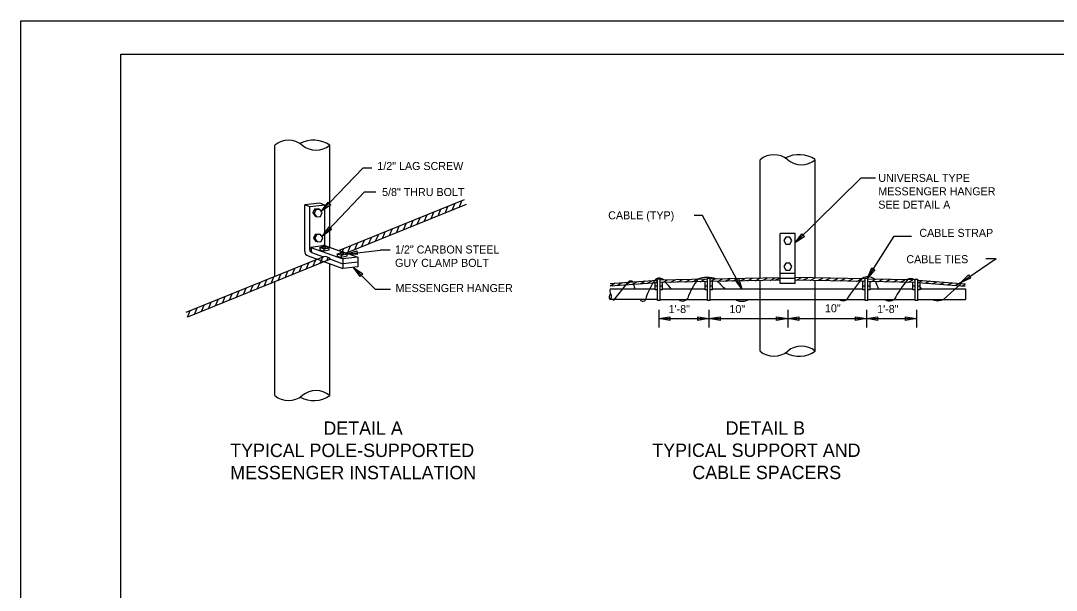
# Model space of a CAD drawing. Extents: x 1299104.8 to 1299141.6, y 239639.8 to 239661.8.
# Drawn here: x 1299104.8 to 1299120.32, y 239653.26 to 239661.79 of the extents above; entities that cross this region are included whole.
import ezdxf

# ---------------------------------------------------------------- set-up
doc = ezdxf.new("R2010")
doc.units = 0
for name, color, linetype in [('DIM TXT', 7, 'Continuous'), ('GS_plotshape_p', 7, 'Continuous'), ('Level 1', 7, 'Continuous')]:
    doc.layers.add(name, color=color, linetype=linetype)

msp = doc.modelspace()

# ---------------------------------------------------------------- linework, layer by layer
at = {"layer": 'DIM TXT'}
for p, q in [((1299108.609, 239657.959), (1299108.609, 239659.926)), ((1299109.434, 239658.399), (1299109.434, 239659.926)), ((1299115.885, 239657.936), (1299115.885, 239659.709)), ((1299116.71, 239657.938), (1299116.71, 239659.709)), ((1299109.928, 239659.584), (1299109.312, 239658.936)), ((1299110.066, 239659.584), (1299109.928, 239659.584)), ((1299116.41, 239658.462), (1299117.396, 239659.436)), ((1299117.396, 239659.436), (1299117.611, 239659.436)), ((1299109.955, 239659.227), (1299109.325, 239658.566)), ((1299109.955, 239659.227), (1299110.125, 239659.227)), ((1299109.284, 239659.056), (1299109.059, 239659.032)), ((1299109.059, 239658.338), (1299109.059, 239659.032)), ((1299109.134, 239659.002), (1299109.059, 239659.032)), ((1299109.359, 239659.026), (1299109.134, 239659.002)), ((1299109.359, 239659.026), (1299109.284, 239659.056)), ((1299109.359, 239658.426), (1299109.359, 239659.026)), ((1299111.448, 239659.106), (1299109.573, 239658.348)), ((1299111.477, 239659.036), (1299109.678, 239658.31)), ((1299111.164, 239658.91), (1299111.205, 239659.008)), ((1299111.268, 239658.952), (1299111.309, 239659.05)), ((1299111.372, 239658.994), (1299111.414, 239659.092)), ((1299109.134, 239658.357), (1299109.134, 239659.002)), ((1299109.198, 239658.904), (1299109.178, 239658.911)), ((1299109.223, 239658.959), (1299109.203, 239658.966)), ((1299109.233, 239658.854), (1299109.214, 239658.862)), ((1299109.283, 239658.965), (1299109.264, 239658.972)), ((1299110.851, 239658.784), (1299110.892, 239658.881)), ((1299110.955, 239658.826), (1299110.996, 239658.923)), ((1299111.059, 239658.868), (1299111.101, 239658.966)), ((1299115.018, 239658.875), (1299114.897, 239658.875)), ((1299115.612, 239657.773), (1299115.018, 239658.875)), ((1299110.434, 239658.615), (1299110.475, 239658.713)), ((1299110.538, 239658.657), (1299110.579, 239658.755)), ((1299110.642, 239658.699), (1299110.684, 239658.797)), ((1299110.746, 239658.741), (1299110.788, 239658.839)), ((1299109.233, 239658.582), (1299109.214, 239658.59)), ((1299109.293, 239658.588), (1299109.274, 239658.596)), ((1299110.016, 239658.446), (1299110.058, 239658.544)), ((1299110.121, 239658.489), (1299110.162, 239658.586)), ((1299110.225, 239658.531), (1299110.266, 239658.628)), ((1299110.329, 239658.573), (1299110.371, 239658.671)), ((1299116.185, 239657.853), (1299116.185, 239658.603)), ((1299116.41, 239658.603), (1299116.185, 239658.603)), ((1299116.267, 239658.55), (1299116.237, 239658.497)), ((1299116.327, 239658.55), (1299116.267, 239658.55)), ((1299116.358, 239658.498), (1299116.327, 239658.55)), ((1299116.41, 239657.853), (1299116.41, 239658.603)), ((1299117.493, 239657.934), (1299117.891, 239658.565)), ((1299117.891, 239658.565), (1299118.154, 239658.565)), ((1299109.359, 239658.426), (1299109.151, 239658.396)), ((1299109.151, 239658.396), (1299109.628, 239658.222)), ((1299109.151, 239658.396), (1299109.159, 239658.321)), ((1299109.208, 239658.527), (1299109.189, 239658.534)), ((1299109.243, 239658.478), (1299109.224, 239658.485)), ((1299109.286, 239658.396), (1299109.331, 239658.407)), ((1299109.286, 239658.396), (1299109.351, 239658.372)), ((1299109.286, 239658.396), (1299109.286, 239658.361)), ((1299109.331, 239658.394), (1299109.331, 239658.417)), ((1299109.351, 239658.373), (1299109.425, 239658.39)), ((1299109.359, 239658.426), (1299109.622, 239658.331)), ((1299109.372, 239658.392), (1299109.372, 239658.417)), ((1299109.372, 239658.409), (1299109.425, 239658.39)), ((1299109.425, 239658.355), (1299109.425, 239658.39)), ((1299109.703, 239658.32), (1299109.745, 239658.418)), ((1299109.808, 239658.362), (1299109.849, 239658.46)), ((1299109.912, 239658.404), (1299109.953, 239658.502)), ((1299116.237, 239658.497), (1299116.267, 239658.445)), ((1299116.267, 239658.445), (1299116.328, 239658.445)), ((1299116.328, 239658.445), (1299116.358, 239658.498)), ((1299109.342, 239658.255), (1299107.276, 239657.42)), ((1299109.109, 239658.268), (1299109.628, 239658.079)), ((1299109.159, 239658.321), (1299109.342, 239658.255)), ((1299109.286, 239658.361), (1299109.351, 239658.338)), ((1299109.286, 239658.151), (1299109.328, 239658.249)), ((1299109.351, 239658.338), (1299109.351, 239658.372)), ((1299109.425, 239658.355), (1299109.351, 239658.338)), ((1299109.39, 239658.194), (1299109.412, 239658.245)), ((1299109.547, 239658.301), (1299109.601, 239658.314)), ((1299109.547, 239658.301), (1299109.547, 239658.266)), ((1299109.547, 239658.301), (1299109.612, 239658.278)), ((1299109.547, 239658.266), (1299109.612, 239658.243)), ((1299109.601, 239658.3), (1299109.601, 239658.324)), ((1299109.612, 239658.278), (1299109.695, 239658.297)), ((1299109.612, 239658.243), (1299109.612, 239658.278)), ((1299109.695, 239658.262), (1299109.612, 239658.243)), ((1299109.621, 239658.331), (1299109.64, 239658.376)), ((1299109.853, 239658.247), (1299109.628, 239658.222)), ((1299109.641, 239658.299), (1299109.641, 239658.324)), ((1299109.641, 239658.317), (1299109.695, 239658.297)), ((1299109.644, 239658.322), (1299109.853, 239658.247)), ((1299109.677, 239658.293), (1299110.189, 239658.355)), ((1299109.695, 239658.262), (1299109.695, 239658.297)), ((1299109.853, 239658.247), (1299109.853, 239658.103)), ((1299110.338, 239658.355), (1299110.189, 239658.355)), ((1299118.886, 239657.866), (1299119.423, 239658.23)), ((1299119.268, 239658.23), (1299119.423, 239658.23)), ((1299109.447, 239658.217), (1299107.304, 239657.351)), ((1299108.869, 239657.983), (1299108.91, 239658.081)), ((1299108.973, 239658.025), (1299109.015, 239658.123)), ((1299109.078, 239658.067), (1299109.119, 239658.165)), ((1299109.182, 239658.109), (1299109.223, 239658.207)), ((1299109.434, 239656.176), (1299109.434, 239658.149)), ((1299109.447, 239658.217), (1299109.628, 239658.151)), ((1299109.628, 239658.222), (1299109.628, 239658.079)), ((1299109.853, 239658.175), (1299109.628, 239658.151)), ((1299109.853, 239658.103), (1299109.628, 239658.079)), ((1299110.12, 239657.764), (1299109.79, 239658.096)), ((1299108.556, 239657.856), (1299108.597, 239657.954)), ((1299108.66, 239657.899), (1299108.702, 239657.996)), ((1299108.765, 239657.941), (1299108.806, 239658.038)), ((1299114.347, 239657.6), (1299114.347, 239657.924)), ((1299114.347, 239657.924), (1299114.385, 239657.924)), ((1299115.096, 239657.921), (1299114.384, 239657.907)), ((1299114.385, 239657.6), (1299114.385, 239657.924)), ((1299114.985, 239657.881), (1299115.059, 239657.92)), ((1299115.097, 239657.937), (1299115.135, 239657.937)), ((1299115.097, 239657.6), (1299115.097, 239657.937)), ((1299116.184, 239657.942), (1299115.134, 239657.921)), ((1299115.135, 239657.6), (1299115.135, 239657.937)), ((1299115.135, 239657.884), (1299115.209, 239657.923)), ((1299115.247, 239657.886), (1299115.321, 239657.925)), ((1299115.36, 239657.888), (1299115.434, 239657.927)), ((1299115.472, 239657.89), (1299115.546, 239657.929)), ((1299115.585, 239657.893), (1299115.659, 239657.932)), ((1299115.697, 239657.894), (1299115.771, 239657.933)), ((1299115.81, 239657.897), (1299115.884, 239657.936)), ((1299115.922, 239657.899), (1299115.996, 239657.938)), ((1299116.035, 239657.901), (1299116.109, 239657.94)), ((1299116.11, 239657.903), (1299116.183, 239657.939)), ((1299116.41, 239658.003), (1299116.185, 239658.003)), ((1299116.41, 239657.928), (1299116.185, 239657.928)), ((1299117.461, 239657.923), (1299116.411, 239657.944)), ((1299116.428, 239657.907), (1299116.503, 239657.944)), ((1299116.523, 239657.904), (1299116.598, 239657.94)), ((1299116.635, 239657.902), (1299116.711, 239657.938)), ((1299116.747, 239657.9), (1299116.823, 239657.936)), ((1299116.86, 239657.898), (1299116.936, 239657.934)), ((1299116.972, 239657.895), (1299117.048, 239657.931)), ((1299117.085, 239657.893), (1299117.161, 239657.929)), ((1299117.197, 239657.891), (1299117.273, 239657.927)), ((1299117.33, 239657.885), (1299117.405, 239657.923)), ((1299117.46, 239657.6), (1299117.46, 239657.934)), ((1299117.46, 239657.934), (1299117.497, 239657.934)), ((1299117.497, 239657.6), (1299117.497, 239657.934)), ((1299118.21, 239657.908), (1299117.498, 239657.922)), ((1299118.21, 239657.6), (1299118.21, 239657.921)), ((1299118.21, 239657.921), (1299118.247, 239657.921)), ((1299118.247, 239657.6), (1299118.247, 239657.921)), ((1299108.139, 239657.688), (1299108.18, 239657.786)), ((1299108.243, 239657.73), (1299108.284, 239657.828)), ((1299108.347, 239657.772), (1299108.389, 239657.87)), ((1299108.452, 239657.814), (1299108.493, 239657.912)), ((1299108.609, 239656.176), (1299108.609, 239657.878)), ((1299113.635, 239657.857), (1299114.346, 239657.907)), ((1299113.635, 239657.773), (1299114.31, 239657.773)), ((1299113.636, 239657.82), (1299114.347, 239657.87)), ((1299113.636, 239657.82), (1299113.71, 239657.863)), ((1299113.691, 239657.607), (1299113.906, 239657.876)), ((1299113.748, 239657.828), (1299113.822, 239657.87)), ((1299113.86, 239657.836), (1299113.934, 239657.878)), ((1299113.906, 239657.876), (1299113.928, 239657.893)), ((1299113.928, 239657.893), (1299113.956, 239657.897)), ((1299113.956, 239657.897), (1299113.968, 239657.895)), ((1299113.968, 239657.895), (1299113.972, 239657.881)), ((1299113.973, 239657.843), (1299114.047, 239657.886)), ((1299113.985, 239657.844), (1299113.985, 239657.842)), ((1299114.085, 239657.851), (1299114.159, 239657.894)), ((1299114.198, 239657.859), (1299114.271, 239657.902)), ((1299114.31, 239657.867), (1299114.347, 239657.889)), ((1299114.31, 239657.758), (1299114.31, 239657.868)), ((1299114.347, 239657.814), (1299114.31, 239657.814)), ((1299115.097, 239657.883), (1299114.385, 239657.87)), ((1299114.422, 239657.814), (1299114.385, 239657.814)), ((1299114.422, 239657.87), (1299114.497, 239657.909)), ((1299114.422, 239657.758), (1299114.422, 239657.87)), ((1299114.422, 239657.773), (1299115.06, 239657.773)), ((1299114.535, 239657.872), (1299114.609, 239657.911)), ((1299114.647, 239657.875), (1299114.722, 239657.914)), ((1299114.76, 239657.877), (1299114.834, 239657.916)), ((1299114.872, 239657.879), (1299114.947, 239657.918)), ((1299115.06, 239657.758), (1299115.06, 239657.883)), ((1299115.097, 239657.814), (1299115.06, 239657.814)), ((1299116.184, 239657.904), (1299115.135, 239657.884)), ((1299115.172, 239657.814), (1299115.135, 239657.814)), ((1299115.172, 239657.758), (1299115.172, 239657.885)), ((1299115.172, 239657.773), (1299117.422, 239657.773)), ((1299115.885, 239656.841), (1299115.885, 239657.898)), ((1299116.41, 239657.853), (1299116.185, 239657.853)), ((1299116.41, 239657.87), (1299116.41, 239657.908)), ((1299117.46, 239657.885), (1299116.41, 239657.907)), ((1299116.71, 239656.841), (1299116.71, 239657.901)), ((1299117.422, 239657.758), (1299117.422, 239657.886)), ((1299117.46, 239657.814), (1299117.422, 239657.814)), ((1299117.424, 239657.885), (1299117.462, 239657.904)), ((1299118.21, 239657.87), (1299117.497, 239657.885)), ((1299117.535, 239657.814), (1299117.497, 239657.814)), ((1299117.535, 239657.758), (1299117.535, 239657.884)), ((1299117.535, 239657.773), (1299118.172, 239657.773)), ((1299117.541, 239657.881), (1299117.616, 239657.919)), ((1299117.647, 239657.882), (1299117.723, 239657.918)), ((1299117.76, 239657.879), (1299117.835, 239657.915)), ((1299117.872, 239657.877), (1299117.948, 239657.913)), ((1299117.985, 239657.875), (1299118.06, 239657.911)), ((1299118.097, 239657.872), (1299118.173, 239657.908)), ((1299118.172, 239657.758), (1299118.172, 239657.87)), ((1299118.21, 239657.814), (1299118.172, 239657.814)), ((1299118.247, 239657.87), (1299118.324, 239657.902)), ((1299118.247, 239657.87), (1299118.958, 239657.815)), ((1299118.285, 239657.814), (1299118.247, 239657.814)), ((1299118.249, 239657.907), (1299118.96, 239657.852)), ((1299118.285, 239657.758), (1299118.285, 239657.869)), ((1299118.285, 239657.773), (1299118.96, 239657.773)), ((1299118.358, 239657.861), (1299118.434, 239657.893)), ((1299118.469, 239657.853), (1299118.545, 239657.885)), ((1299118.58, 239657.844), (1299118.656, 239657.876)), ((1299118.897, 239657.857), (1299118.634, 239657.613)), ((1299118.69, 239657.836), (1299118.767, 239657.867)), ((1299118.801, 239657.827), (1299118.877, 239657.859)), ((1299118.912, 239657.819), (1299118.959, 239657.838)), ((1299118.96, 239657.773), (1299118.96, 239657.613)), ((1299107.72, 239657.519), (1299107.761, 239657.616)), ((1299107.824, 239657.561), (1299107.866, 239657.658)), ((1299107.929, 239657.603), (1299107.97, 239657.701)), ((1299108.034, 239657.646), (1299108.076, 239657.743)), ((1299110.345, 239657.764), (1299110.12, 239657.764)), ((1299114.347, 239657.613), (1299113.635, 239657.613)), ((1299114.347, 239657.758), (1299114.31, 239657.758)), ((1299114.422, 239657.758), (1299114.385, 239657.758)), ((1299114.385, 239657.613), (1299115.097, 239657.613)), ((1299115.097, 239657.758), (1299115.06, 239657.758)), ((1299115.172, 239657.758), (1299115.135, 239657.758)), ((1299115.135, 239657.613), (1299116.834, 239657.613)), ((1299116.834, 239657.613), (1299117.46, 239657.613)), ((1299117.46, 239657.758), (1299117.422, 239657.758)), ((1299117.535, 239657.758), (1299117.497, 239657.758)), ((1299117.497, 239657.613), (1299118.21, 239657.613)), ((1299118.21, 239657.758), (1299118.172, 239657.758)), ((1299118.285, 239657.758), (1299118.247, 239657.758)), ((1299118.247, 239657.613), (1299118.96, 239657.613)), ((1299107.407, 239657.392), (1299107.448, 239657.49)), ((1299107.511, 239657.434), (1299107.553, 239657.532)), ((1299107.616, 239657.477), (1299107.657, 239657.574)), ((1299114.385, 239657.6), (1299114.347, 239657.6)), ((1299114.366, 239657.46), (1299114.366, 239657.197)), ((1299115.135, 239657.6), (1299115.097, 239657.6)), ((1299115.116, 239657.46), (1299115.116, 239657.197)), ((1299116.297, 239657.462), (1299116.297, 239657.197)), ((1299117.497, 239657.6), (1299117.46, 239657.6)), ((1299117.478, 239657.46), (1299117.478, 239657.197)), ((1299118.247, 239657.6), (1299118.21, 239657.6)), ((1299118.228, 239657.46), (1299118.228, 239657.197)), ((1299107.303, 239657.35), (1299107.344, 239657.448)), ((1299114.366, 239657.328), (1299118.228, 239657.328))]:
    msp.add_line(p, q, dxfattribs=at)
for points in [[(1299109.41, 239659.074), (1299109.448, 239659.035), (1299109.312, 239658.936)], [(1299109.423, 239658.703), (1299109.462, 239658.665), (1299109.325, 239658.566)], [(1299116.511, 239658.597), (1299116.549, 239658.558), (1299116.41, 239658.462)], [(1299109.839, 239658.342), (1299109.846, 239658.288), (1299109.677, 239658.293)], [(1299109.927, 239657.997), (1299109.888, 239657.959), (1299109.79, 239658.096)], [(1299117.558, 239658.09), (1299117.605, 239658.061), (1299117.493, 239657.934)], [(1299115.511, 239657.908), (1299115.559, 239657.933), (1299115.612, 239657.773)], [(1299119.009, 239657.982), (1299119.039, 239657.936), (1299118.886, 239657.866)], [(1299114.533, 239657.356), (1299114.533, 239657.301), (1299114.366, 239657.328)], [(1299114.949, 239657.301), (1299114.949, 239657.356), (1299115.116, 239657.328)], [(1299115.283, 239657.356), (1299115.283, 239657.301), (1299115.116, 239657.328)], [(1299116.13, 239657.301), (1299116.13, 239657.356), (1299116.297, 239657.328)], [(1299116.464, 239657.356), (1299116.464, 239657.301), (1299116.297, 239657.328)], [(1299117.312, 239657.301), (1299117.312, 239657.356), (1299117.478, 239657.328)], [(1299117.645, 239657.356), (1299117.645, 239657.301), (1299117.478, 239657.328)], [(1299118.062, 239657.301), (1299118.062, 239657.356), (1299118.228, 239657.328)]]:
    msp.add_lwpolyline(points, close=True, dxfattribs=at)
for points in [[(1299109.203, 239658.966), (1299109.178, 239658.911), (1299109.214, 239658.862)], [(1299109.223, 239658.959), (1299109.198, 239658.904), (1299109.233, 239658.854), (1299109.293, 239658.86), (1299109.318, 239658.916)], [(1299109.264, 239658.972), (1299109.203, 239658.966)], [(1299109.318, 239658.916), (1299109.283, 239658.965), (1299109.223, 239658.959)], [(1299109.214, 239658.59), (1299109.189, 239658.534), (1299109.224, 239658.485)], [(1299109.233, 239658.582), (1299109.208, 239658.527), (1299109.243, 239658.478), (1299109.304, 239658.484), (1299109.329, 239658.539)], [(1299109.274, 239658.596), (1299109.214, 239658.59)], [(1299109.329, 239658.539), (1299109.293, 239658.588), (1299109.233, 239658.582)], [(1299116.267, 239658.16), (1299116.237, 239658.108), (1299116.267, 239658.055), (1299116.327, 239658.055), (1299116.358, 239658.107)], [(1299116.358, 239658.107), (1299116.328, 239658.16), (1299116.267, 239658.16)]]:
    msp.add_lwpolyline(points, dxfattribs=at)
for centre, radius, start, end in [((1299108.816, 239659.68), 0.321, 50.0338, 129.9662), ((1299109.191, 239659.567), 0.434, 55.7945, 117.8517), ((1299109.228, 239660.172), 0.321, 230.0338, 309.9662), ((1299116.091, 239659.463), 0.321, 50.0338, 129.9662), ((1299116.466, 239659.351), 0.434, 55.7945, 117.8517), ((1299116.503, 239659.955), 0.321, 230.0338, 309.9662), ((1299109.334, 239658.417), 0.00233, 126.4408, 180), ((1299109.334, 239658.417), 0.00233, 180, 233.5592), ((1299109.334, 239658.394), 0.00233, 180, 233.5592), ((1299109.342, 239658.406), 0.0166, 107.0057, 126.4408), ((1299109.342, 239658.429), 0.0166, 233.5592, 252.9943), ((1299109.342, 239658.405), 0.0166, 233.5592, 252.9943), ((1299109.348, 239658.387), 0.0362, 97.2199, 107.0057), ((1299109.348, 239658.448), 0.0362, 252.9943, 262.7801), ((1299109.348, 239658.424), 0.0362, 252.9943, 262.7801), ((1299109.352, 239658.357), 0.0665, 90, 97.2199), ((1299109.352, 239658.478), 0.0665, 262.7801, 270), ((1299109.352, 239658.454), 0.0665, 262.7801, 270), ((1299109.352, 239658.357), 0.0665, 82.7801, 90), ((1299109.352, 239658.478), 0.0665, 270, 277.2199), ((1299109.352, 239658.454), 0.0665, 270, 277.2199), ((1299109.355, 239658.387), 0.0362, 72.9943, 82.7801), ((1299109.355, 239658.448), 0.0362, 277.2199, 287.0057), ((1299109.355, 239658.424), 0.0362, 277.2199, 287.0057), ((1299109.361, 239658.406), 0.0166, 53.5592, 72.9943), ((1299109.361, 239658.429), 0.0166, 287.0057, 306.4408), ((1299109.361, 239658.405), 0.0166, 287.0057, 310.6149), ((1299109.37, 239658.417), 0.00233, 0, 53.5592), ((1299109.37, 239658.417), 0.00233, 306.4408, 360), ((1299109.134, 239658.338), 0.075, 180, 250), ((1299109.172, 239658.357), 0.0375, 180, 250), ((1299109.362, 239658.147), 0.11, 39.2889, 100.7111), ((1299109.603, 239658.324), 0.00233, 126.4408, 180), ((1299109.603, 239658.324), 0.00233, 180, 233.5592), ((1299109.603, 239658.3), 0.00233, 180, 233.5592), ((1299109.612, 239658.312), 0.0166, 107.0057, 126.4408), ((1299109.612, 239658.335), 0.0166, 233.5592, 252.9943), ((1299109.612, 239658.311), 0.0166, 233.5592, 252.9943), ((1299109.617, 239658.293), 0.0362, 97.2199, 107.0057), ((1299109.617, 239658.354), 0.0362, 252.9943, 262.7801), ((1299109.617, 239658.33), 0.0362, 252.9943, 262.7801), ((1299109.621, 239658.263), 0.0665, 90, 97.2199), ((1299109.621, 239658.384), 0.0665, 262.7801, 270), ((1299109.621, 239658.36), 0.0665, 262.7801, 270), ((1299109.621, 239658.263), 0.0665, 82.7801, 90), ((1299109.621, 239658.384), 0.0665, 270, 277.2199), ((1299109.621, 239658.36), 0.0665, 270, 277.2199), ((1299109.625, 239658.293), 0.0362, 72.9943, 82.7801), ((1299109.625, 239658.354), 0.0362, 277.2199, 287.0057), ((1299109.625, 239658.33), 0.0362, 277.2199, 287.0057), ((1299109.631, 239658.312), 0.0166, 53.5592, 72.9943), ((1299109.631, 239658.335), 0.0166, 287.0057, 306.4408), ((1299109.631, 239658.311), 0.0166, 287.0057, 310.6149), ((1299109.639, 239658.324), 0.00233, 0, 53.5592), ((1299109.639, 239658.324), 0.00233, 306.4408, 360), ((1299115.044, 239657.368), 0.911, 142.1762, 164.7612), ((1299114.367, 239657.837), 0.0988, 46.2237, 115.4192), ((1299115.096, 239657.535), 0.411, 72.0485, 111.3197), ((1299119.787, 239655.942), 3.096, 139.9879, 147.4122), ((1299117.5, 239657.791), 0.164, 53.269, 120.7369), ((1299118.62, 239658.261), 1.077, 198.28, 198.4324), ((1299118.14, 239657.829), 0.0994, 59.3243, 116.8613), ((1299113.714, 239657.745), 0.0843, 161.1078, 214.9891), ((1299114.794, 239658.067), 0.84, 195.5298, 200.5394), ((1299112.147, 239655.839), 3.085, 38.809, 41.1992), ((1299115.782, 239657.281), 1.046, 142.4516, 160.1129), ((1299122.75, 239665.21), 10.486, 224.2981, 225.1705), ((1299118.62, 239658.261), 1.077, 200.5651, 206.9437), ((1299120.036, 239656.397), 2.465, 141.9153, 150.4065), ((1299119.531, 239658.894), 1.66, 216.1858, 216.4475), ((1299119.531, 239658.894), 1.66, 221.345, 222.4994), ((1299118.883, 239657.85), 0.0156, 25.6417, 145.4998), ((1299113.684, 239657.653), 0.0633, 130.635, 218.6724), ((1299113.594, 239657.661), 0.0628, 310.4563, 34.9891), ((1299113.695, 239657.637), 0.0298, 232.2209, 262.4145), ((1299114.794, 239658.067), 0.84, 212.7276, 213.8978), ((1299112.147, 239655.839), 3.085, 34.7618, 35.1045), ((1299114.717, 239657.688), 0.0963, 248.6342, 327.6813), ((1299122.75, 239665.21), 10.486, 226.4195, 226.4638), ((1299115.609, 239657.773), 0.185, 243.5908, 302.8236), ((1299118.186, 239658.541), 1.452, 219.7247, 220.0936), ((1299118.62, 239658.261), 1.077, 216.9507, 217.5898), ((1299117.819, 239657.737), 0.143, 248.735, 300.7078), ((1299119.531, 239658.894), 1.66, 230.4962, 231.0176), ((1299118.543, 239657.878), 0.28, 258.3891, 289.0172), ((1299114.127, 239657.642), 0.0524, 235.7984, 317.5273), ((1299117.124, 239657.709), 0.113, 244.9857, 298.5827), ((1299116.091, 239657.087), 0.321, 230.0338, 309.9662), ((1299116.466, 239657.199), 0.434, 242.1483, 304.2055), ((1299116.503, 239656.595), 0.321, 50.0338, 129.9662), ((1299109.228, 239655.93), 0.321, 50.0338, 129.9662), ((1299108.816, 239656.422), 0.321, 230.0338, 309.9662), ((1299109.191, 239656.535), 0.434, 242.1483, 304.2055)]:
    msp.add_arc(centre, radius, start, end, dxfattribs=at)
at = {"layer": 'GS_plotshape_p'}
msp.add_lwpolyline([(1299104.802, 239661.791), (1299138.802, 239661.791), (1299138.802, 239639.791), (1299104.802, 239639.791)], close=True, dxfattribs=at)
at = {"layer": 'Level 1'}
msp.add_lwpolyline([(1299138.302, 239640.291), (1299106.302, 239640.291), (1299106.302, 239661.291), (1299138.302, 239661.291)], close=True, dxfattribs=at)

# ---------------------------------------------------------------- texts
at = {"layer": 'DIM TXT'}
for s, height, p in [('1/2" LAG SCREW', 0.12, (1299110.147, 239659.555)), ('UNIVERSAL TYPE ', 0.12, (1299117.655, 239659.376)), ('5/8" THRU BOLT', 0.12, (1299110.218, 239659.165)), ('MESSENGER HANGER ', 0.12, (1299117.655, 239659.176)), ('SEE DETAIL A', 0.12, (1299117.655, 239658.976)), ('CABLE (TYP)', 0.12, (1299113.607, 239658.816)), ('CABLE STRAP', 0.12, (1299118.271, 239658.553)), ('1/2" CARBON STEEL ', 0.12, (1299110.412, 239658.304)), ('CABLE TIES', 0.12, (1299118.076, 239658.159)), ('GUY CLAMP BOLT', 0.12, (1299110.412, 239658.104)), ('MESSENGER HANGER', 0.12, (1299110.42, 239657.726)), ('1\'-8"', 0.12, (1299114.512, 239657.412)), ('10"', 0.12, (1299115.424, 239657.412)), ('10"', 0.12, (1299116.856, 239657.424)), ('1\'-8"', 0.12, (1299117.638, 239657.412)), ('DETAIL A', 0.2, (1299109.339, 239655.588)), ('DETAIL B', 0.2, (1299115.368, 239655.59)), ('TYPICAL POLE-SUPPORTED ', 0.2, (1299107.942, 239655.255)), ('TYPICAL SUPPORT AND ', 0.2, (1299114.268, 239655.257)), ('CABLE SPACERS', 0.2, (1299114.869, 239654.924)), ('MESSENGER INSTALLATION', 0.2, (1299107.942, 239654.922))]:
    msp.add_text(s, height=height, dxfattribs=at).set_placement(p)

doc.saveas('drawing.dxf')
